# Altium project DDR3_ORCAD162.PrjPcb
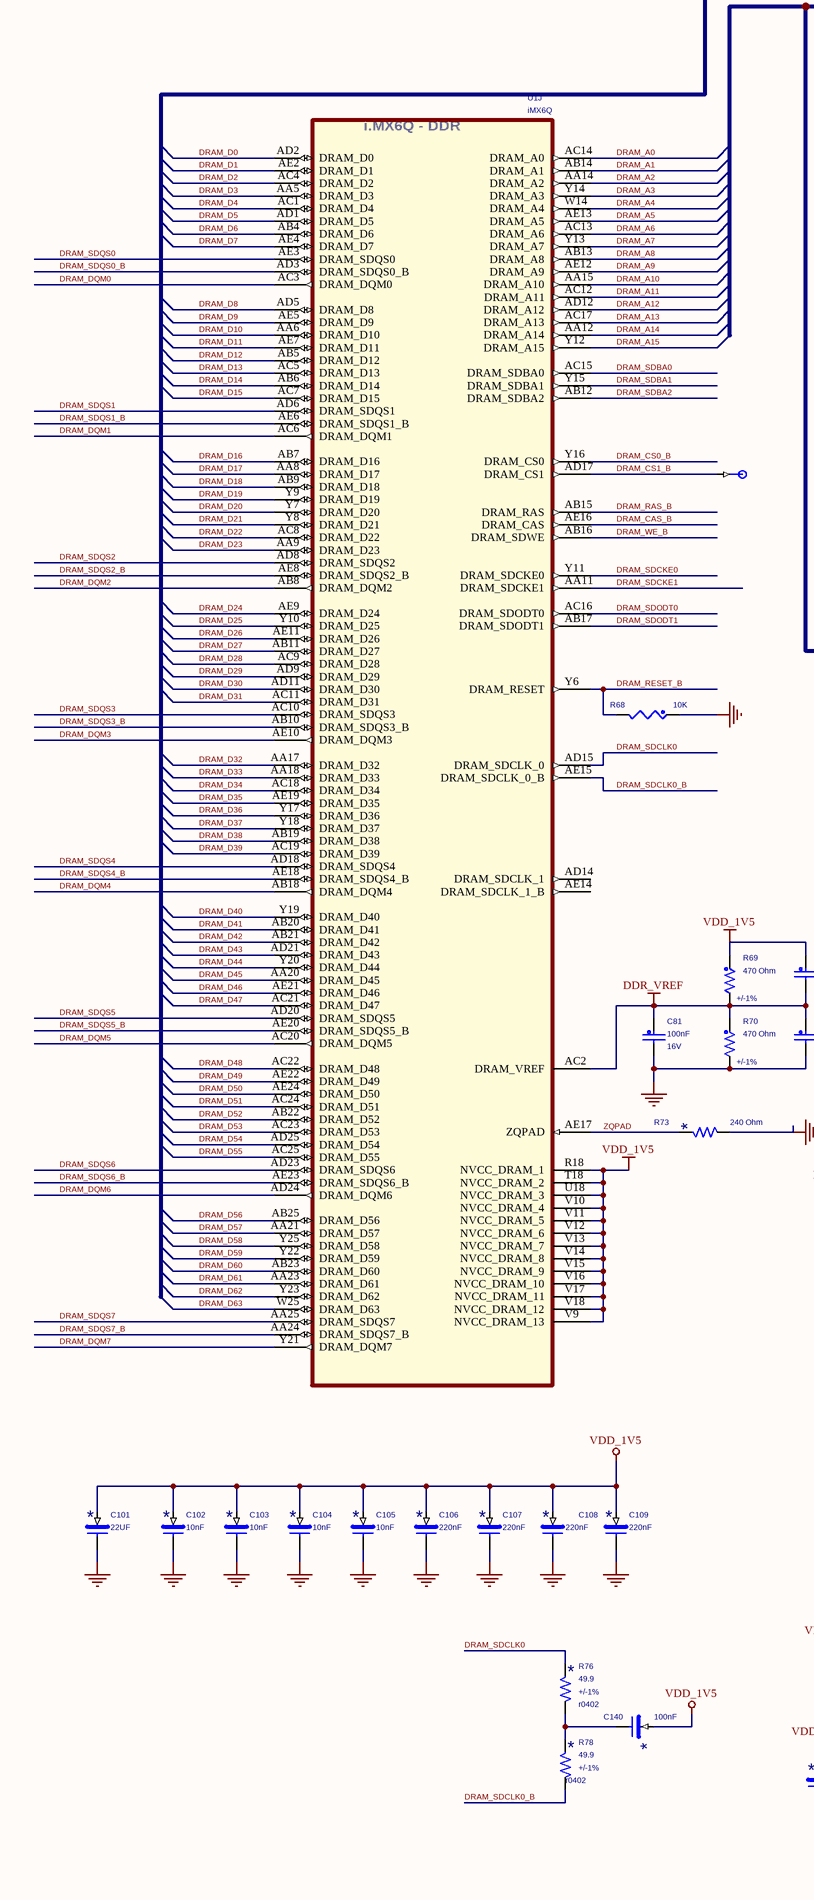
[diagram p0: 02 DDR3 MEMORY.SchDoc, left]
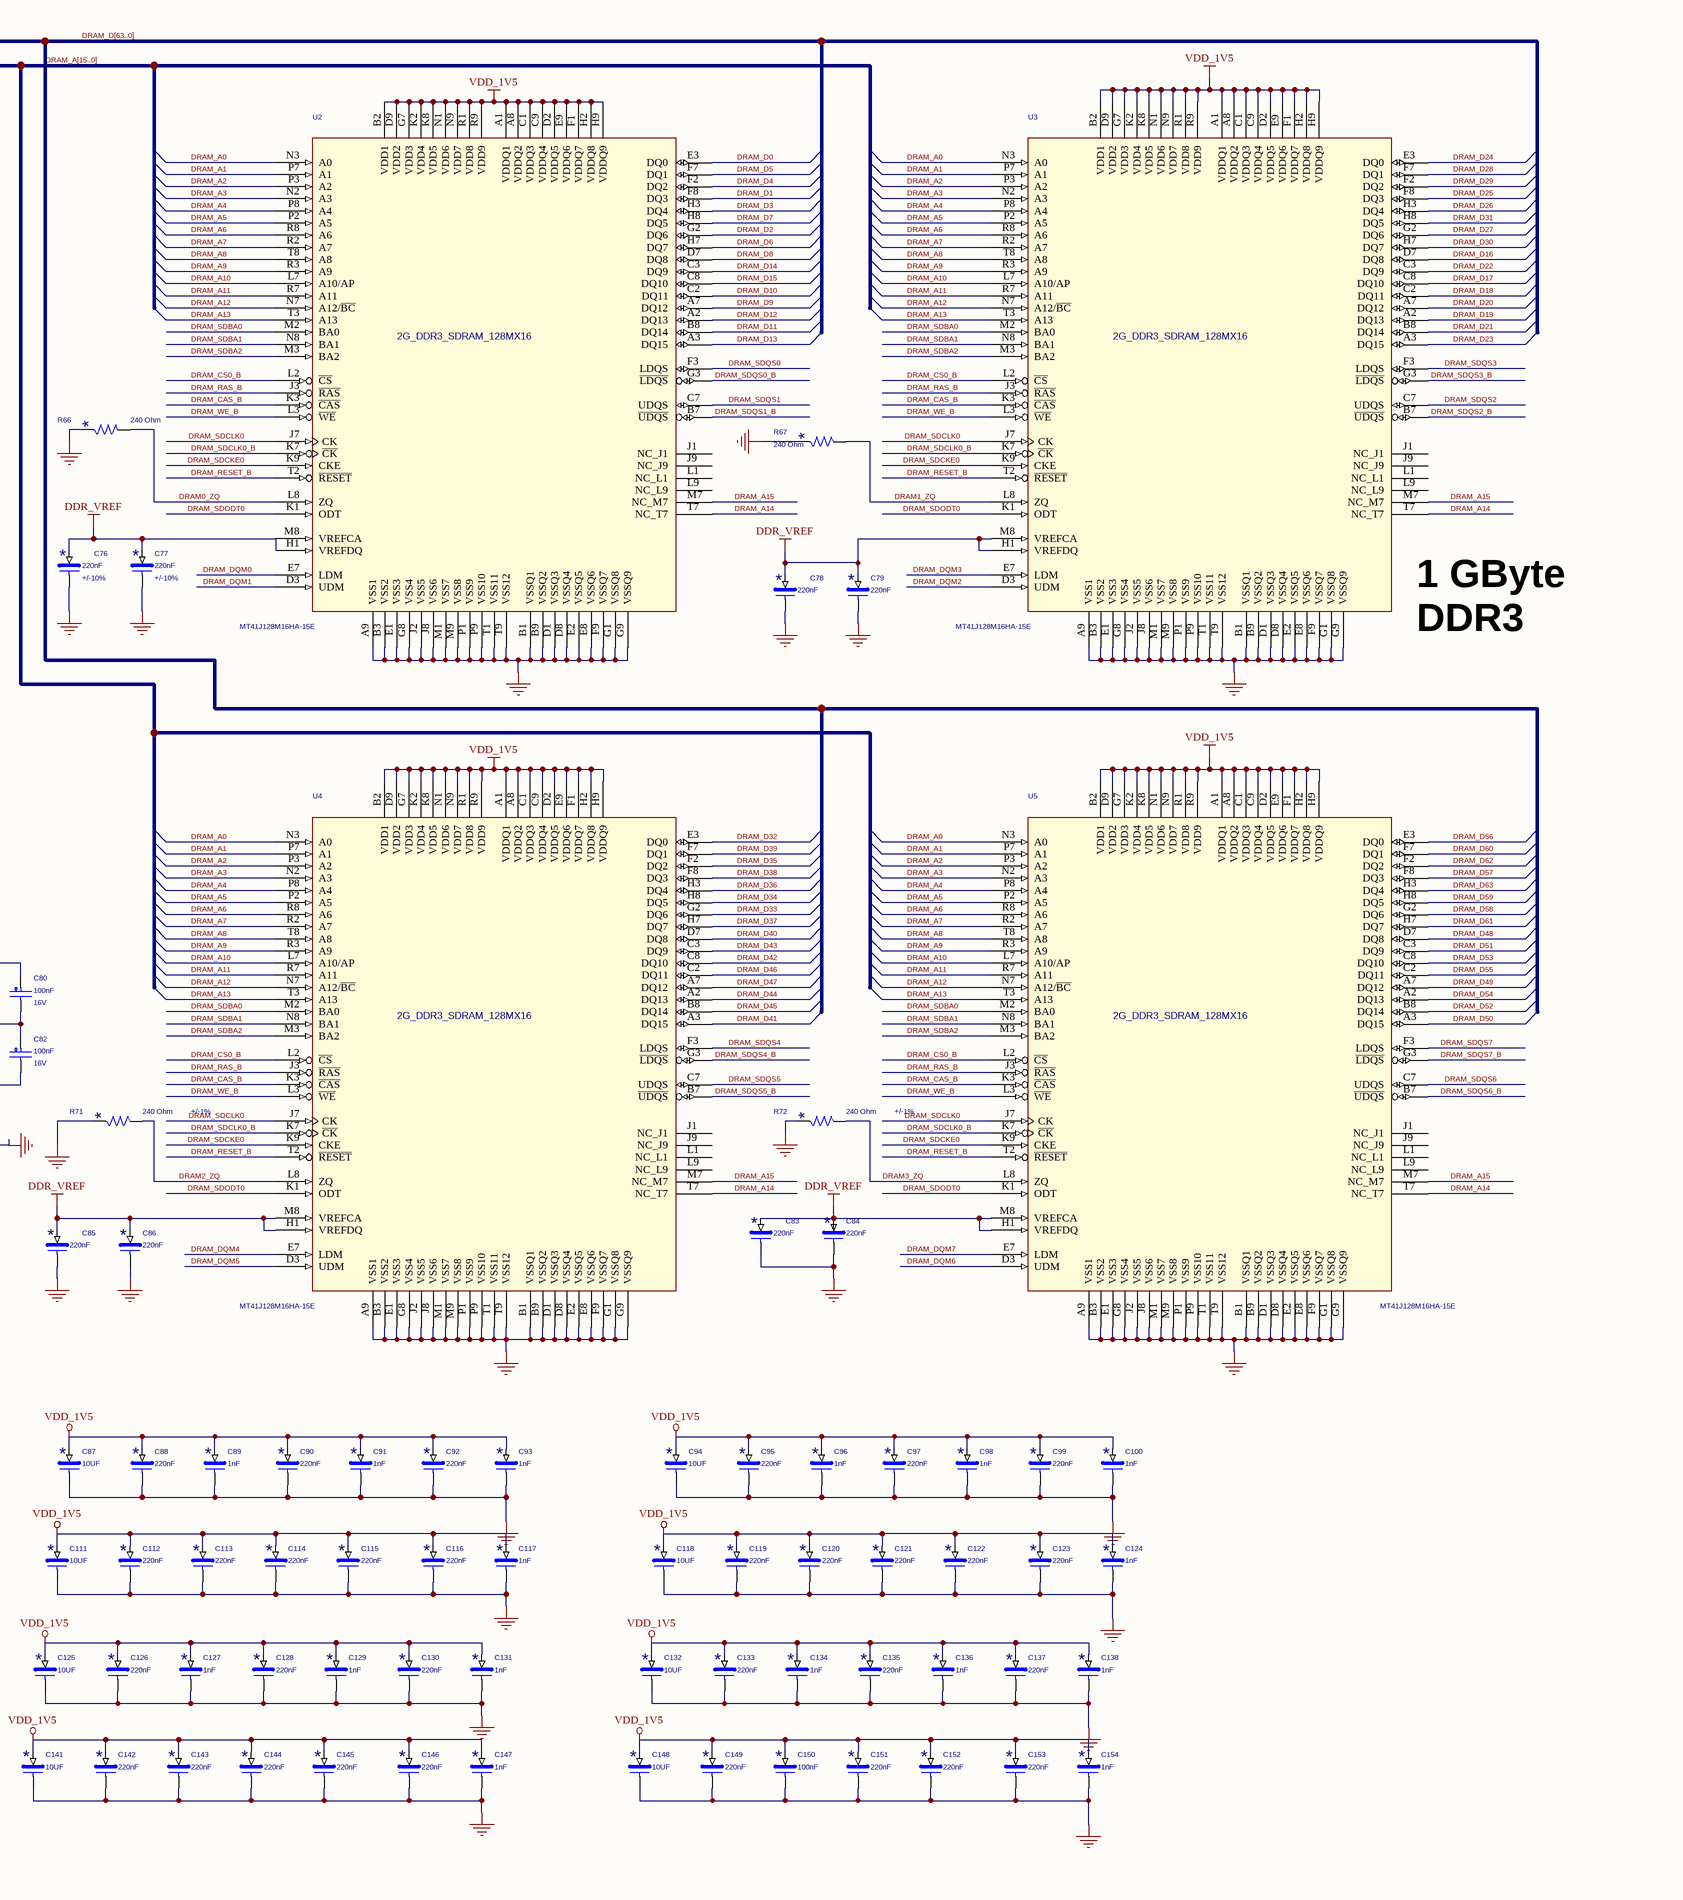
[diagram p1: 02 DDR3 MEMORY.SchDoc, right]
2 sheets, 111 parts. Net scope: global (net labels, ports and power ports of the same name join across sheets).
Sheets:
  02 DDR3 MEMORY.SchDoc
  01 POWER.SchDoc

## Sheet 02 DDR3 MEMORY.SchDoc
size 513 x 386 mm

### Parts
C76  220nF  Tolerance: +/-10%  [C0402]
C77  220nF  Tolerance: +/-10%  [C0402]
C78  220nF  [C0402]
C79  220nF  [C0402]
C80  100nF  WVDC: 16V  [c0402]
C81  100nF  WVDC: 16V  [c0402]
C82  100nF  WVDC: 16V  [c0402]
C83  220nF  [C0402]
C84  220nF  [C0402]
C85  220nF  [C0402]
C86  220nF  [C0402]
C87  10UF  [c0603]
C88  220nF  [C0402]
C89  1nF  [C0402]
C90  220nF  [C0402]
C91  1nF  [C0402]
C92  220nF  [C0402]
C93  1nF  [C0402]
C94  10UF  [c0603]
C95  220nF  [C0402]
C96  1nF  [C0402]
C97  220nF  [C0402]
C98  1nF  [C0402]
C99  220nF  [C0402]
C100  1nF  [C0402]
C101  22UF  [0603_cc]
C102  10nF  [c0402]
C103  10nF  [c0402]
C104  10nF  [c0402]
C105  10nF  [c0402]
C106  220nF  [c0402]
C107  220nF  [c0402]
C108  220nF  [c0402]
C109  220nF  [c0402]
C111  10UF  [c0402]
C112  220nF  [c0402]
C113  220nF  [c0402]
C114  220nF  [c0402]
C115  220nF  [c0402]
C116  220nF  [c0402]
C117  1nF  [c0402]
C118  10UF  [c0603]
C119  220nF  [C0402]
C120  220nF  [C0402]
C121  220nF  [C0402]
C122  220nF  [C0402]
C123  220nF  [C0402]
C124  1nF  [C0402]
C125  10UF  [c0603]
C126  220nF  [C0402]
C127  1nF  [C0402]
C128  220nF  [C0402]
C129  1nF  [C0402]
C130  220nF  [C0402]
C131  1nF  [C0402]
C132  10UF  [c0603]
C133  220nF  [C0402]
C134  1nF  [C0402]
C135  220nF  [C0402]
C136  1nF  [C0402]
C137  220nF  [C0402]
C138  1nF  [C0402]
C140  100nF  [c0402]
C141  10UF  [c0603]
C142  220nF  [C0402]
C143  220nF  [C0402]
C144  220nF  [C0402]
C145  220nF  [C0402]
C146  220nF  [C0402]
C147  1nF  [C0402]
C148  10UF  [c0603]
C149  220nF  [C0402]
C150  100nF  [C0402]
C151  220nF  [C0402]
C152  220nF  [C0402]
C153  220nF  [C0402]
C154  1nF  [C0402]
R66  240 Ohm  [r0402]
R67  240 Ohm  [r0402]
R68  10K  [r0402]
R69  470 Ohm  Tolerance: +/-1%  [r0402]
R70  470 Ohm  Tolerance: +/-1%  [r0402]
R71  240 Ohm  Tolerance: +/-1%  [r0402]
R72  240 Ohm  Tolerance: +/-1%  [r0402]
R73  240 Ohm  [r0402]
R76  49.9  Tolerance: +/-1%  [r0402]
R78  49.9  Tolerance: +/-1%  [r0402]
TP2  TP  [TP]  (value not drawn)
U1  iMX6Q  [skt_bga625_0p8_22x22]  (part J of 12)
U2  MT41J128M16HA-15E  [BGA15X9-96_FS]
U3  MT41J128M16HA-15E  [BGA15X9-96_FS]
U4  MT41J128M16HA-15E  [BGA15X9-96_FS]
U5  MT41J128M16HA-15E  [BGA15X9-96_FS]

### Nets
DDR_VREF: C76.1 C77.1 C78.1 C79.1 C80.2 C81.1 C82.1 C83.1 C84.1 C85.1 C86.1 R69.2 R70.1 U1.AC2(DRAM_VREF) U2.H1(VREFDQ) U2.M8(VREFCA) U3.H1(VREFDQ) U3.M8(VREFCA) U4.H1(VREFDQ) U4.M8(VREFCA) U5.H1(VREFDQ) U5.M8(VREFCA)
GND: C76.2 C77.2 C78.2 C79.2 C81.2 C82.2 C83.2 C84.2 C85.2 C86.2 C87.2 C88.2 C89.2 C90.2 C91.2 C92.2 C93.2 C94.2 C95.2 C96.2 C97.2 C98.2 C99.2 C100.2 C101.2 C102.2 C103.2 C104.2 C105.2 C106.2 C107.2 C108.2 C109.2 C111.2 C112.2 C113.2 C114.2 C115.2 C116.2 C117.2 C118.2 C119.2 C120.2 C121.2 C122.2 C123.2 C124.2 C125.2 C126.2 C127.2 C128.2 C129.2 C130.2 C131.2 C132.2 C133.2 C134.2 C135.2 C136.2 C137.2 C138.2 C141.2 C142.2 C143.2 C144.2 C145.2 C146.2 C147.2 C148.2 C149.2 C150.2 C151.2 C152.2 C153.2 C154.2 R66.1 R67.1 R68.1 R70.2 R71.1 R72.1 R73.2 U2.A9(VSS1) U2.B1(VSSQ1) U2.B3(VSS2) U2.B9(VSSQ2) U2.D1(VSSQ3) U2.D8(VSSQ4) U2.E1(VSS3) U2.E2(VSSQ5) U2.E8(VSSQ6) U2.F9(VSSQ7) U2.G1(VSSQ8) U2.G8(VSS4) U2.G9(VSSQ9) U2.J2(VSS5) U2.J8(VSS6) U2.M1(VSS7) U2.M9(VSS8) U2.P1(VSS9) U2.P9(VSS10) U2.T1(VSS11) U2.T9(VSS12) U3.A9(VSS1) U3.B1(VSSQ1) U3.B3(VSS2) U3.B9(VSSQ2) U3.D1(VSSQ3) U3.D8(VSSQ4) U3.E1(VSS3) U3.E2(VSSQ5) U3.E8(VSSQ6) U3.F9(VSSQ7) U3.G1(VSSQ8) U3.G8(VSS4) U3.G9(VSSQ9) U3.J2(VSS5) U3.J8(VSS6) U3.M1(VSS7) U3.M9(VSS8) U3.P1(VSS9) U3.P9(VSS10) U3.T1(VSS11) U3.T9(VSS12) U4.A9(VSS1) U4.B1(VSSQ1) U4.B3(VSS2) U4.B9(VSSQ2) U4.D1(VSSQ3) U4.D8(VSSQ4) U4.E1(VSS3) U4.E2(VSSQ5) U4.E8(VSSQ6) U4.F9(VSSQ7) U4.G1(VSSQ8) U4.G8(VSS4) U4.G9(VSSQ9) U4.J2(VSS5) U4.J8(VSS6) U4.M1(VSS7) U4.M9(VSS8) U4.P1(VSS9) U4.P9(VSS10) U4.T1(VSS11) U4.T9(VSS12) U5.A9(VSS1) U5.B1(VSSQ1) U5.B3(VSS2) U5.B9(VSSQ2) U5.D1(VSSQ3) U5.D8(VSSQ4) U5.E1(VSS3) U5.E2(VSSQ5) U5.E8(VSSQ6) U5.F9(VSSQ7) U5.G1(VSSQ8) U5.G8(VSS4) U5.G9(VSSQ9) U5.J2(VSS5) U5.J8(VSS6) U5.M1(VSS7) U5.M9(VSS8) U5.P1(VSS9) U5.P9(VSS10) U5.T1(VSS11) U5.T9(VSS12)
VDD_1V5: C80.1 C87.1 C88.1 C89.1 C90.1 C91.1 C92.1 C93.1 C94.1 C95.1 C96.1 C97.1 C98.1 C99.1 C100.1 C101.1 C102.1 C103.1 C104.1 C105.1 C106.1 C107.1 C108.1 C109.1 C111.1 C112.1 C113.1 C114.1 C115.1 C116.1 C117.1 C118.1 C119.1 C120.1 C121.1 C122.1 C123.1 C124.1 C125.1 C126.1 C127.1 C128.1 C129.1 C130.1 C131.1 C132.1 C133.1 C134.1 C135.1 C136.1 C137.1 C138.1 C140.1 C141.1 C142.1 C143.1 C144.1 C145.1 C146.1 C147.1 C148.1 C149.1 C150.1 C151.1 C152.1 C153.1 C154.1 R69.1 U1.R18(NVCC_DRAM_1) U1.T18(NVCC_DRAM_2) U1.U18(NVCC_DRAM_3) U1.V9(NVCC_DRAM_13) U1.V10(NVCC_DRAM_4) U1.V11(NVCC_DRAM_5) U1.V12(NVCC_DRAM_6) U1.V13(NVCC_DRAM_7) U1.V14(NVCC_DRAM_8) U1.V15(NVCC_DRAM_9) U1.V16(NVCC_DRAM_10) U1.V17(NVCC_DRAM_11) U1.V18(NVCC_DRAM_12) U2.A1(VDDQ1) U2.A8(VDDQ2) U2.B2(VDD1) U2.C1(VDDQ3) U2.C9(VDDQ4) U2.D2(VDDQ5) U2.D9(VDD2) U2.E9(VDDQ6) U2.F1(VDDQ7) U2.G7(VDD3) U2.H2(VDDQ8) U2.H9(VDDQ9) U2.K2(VDD4) U2.K8(VDD5) U2.N1(VDD6) U2.N9(VDD7) U2.R1(VDD8) U2.R9(VDD9) U3.A1(VDDQ1) U3.A8(VDDQ2) U3.B2(VDD1) U3.C1(VDDQ3) U3.C9(VDDQ4) U3.D2(VDDQ5) U3.D9(VDD2) U3.E9(VDDQ6) U3.F1(VDDQ7) U3.G7(VDD3) U3.H2(VDDQ8) U3.H9(VDDQ9) U3.K2(VDD4) U3.K8(VDD5) U3.N1(VDD6) U3.N9(VDD7) U3.R1(VDD8) U3.R9(VDD9) U4.A1(VDDQ1) U4.A8(VDDQ2) U4.B2(VDD1) U4.C1(VDDQ3) U4.C9(VDDQ4) U4.D2(VDDQ5) U4.D9(VDD2) U4.E9(VDDQ6) U4.F1(VDDQ7) U4.G7(VDD3) U4.H2(VDDQ8) U4.H9(VDDQ9) U4.K2(VDD4) U4.K8(VDD5) U4.N1(VDD6) U4.N9(VDD7) U4.R1(VDD8) U4.R9(VDD9) U5.A1(VDDQ1) U5.A8(VDDQ2) U5.B2(VDD1) U5.C1(VDDQ3) U5.C9(VDDQ4) U5.D2(VDDQ5) U5.D9(VDD2) U5.E9(VDDQ6) U5.F1(VDDQ7) U5.G7(VDD3) U5.H2(VDDQ8) U5.H9(VDDQ9) U5.K2(VDD4) U5.K8(VDD5) U5.N1(VDD6) U5.N9(VDD7) U5.R1(VDD8) U5.R9(VDD9)
DRAM0_ZQ: R66.2 U2.L8(ZQ)
DRAM1_ZQ: R67.2 U3.L8(ZQ)
DRAM2_ZQ: R71.2 U4.L8(ZQ)
DRAM3_ZQ: R72.2 U5.L8(ZQ)
DRAM_A0: U1.AC14(DRAM_A0) U1.AC22(DRAM_D48) U2.N3(A0) U3.N3(A0) U4.N3(A0) U5.D7(DQ8) U5.N3(A0)  [also labelled DRAM_D48]
DRAM_A1: U1.AB14(DRAM_A1) U1.AE22(DRAM_D49) U2.P7(A1) U3.P7(A1) U4.P7(A1) U5.A7(DQ12) U5.P7(A1)  [also labelled DRAM_D49]
DRAM_A2: U1.AA14(DRAM_A2) U1.AE24(DRAM_D50) U2.P3(A2) U3.P3(A2) U4.P3(A2) U5.A3(DQ15) U5.P3(A2)  [also labelled DRAM_D50]
DRAM_A3: U1.AC24(DRAM_D51) U1.Y14(DRAM_A3) U2.N2(A3) U3.N2(A3) U4.N2(A3) U5.C3(DQ9) U5.N2(A3)  [also labelled DRAM_D51]
DRAM_A4: U1.AB22(DRAM_D52) U1.W14(DRAM_A4) U2.P8(A4) U3.P8(A4) U4.P8(A4) U5.B8(DQ14) U5.P8(A4)  [also labelled DRAM_D52]
DRAM_A5: U1.AC23(DRAM_D53) U1.AE13(DRAM_A5) U2.P2(A5) U3.P2(A5) U4.P2(A5) U5.C8(DQ10) U5.P2(A5)  [also labelled DRAM_D53]
DRAM_A6: U1.AC13(DRAM_A6) U1.AD25(DRAM_D54) U2.R8(A6) U3.R8(A6) U4.R8(A6) U5.A2(DQ13) U5.R8(A6)  [also labelled DRAM_D54]
DRAM_A7: U1.AC25(DRAM_D55) U1.Y13(DRAM_A7) U2.R2(A7) U3.R2(A7) U4.R2(A7) U5.C2(DQ11) U5.R2(A7)  [also labelled DRAM_D55]
DRAM_A8: U1.AB13(DRAM_A8) U1.AB25(DRAM_D56) U2.T8(A8) U3.T8(A8) U4.T8(A8) U5.E3(DQ0) U5.T8(A8)  [also labelled DRAM_D56]
DRAM_A9: U1.AA21(DRAM_D57) U1.AE12(DRAM_A9) U2.R3(A9) U3.R3(A9) U4.R3(A9) U5.F8(DQ3) U5.R3(A9)  [also labelled DRAM_D57]
DRAM_A10: U1.AA15(DRAM_A10) U1.Y25(DRAM_D58) U2.L7(A10/AP) U3.L7(A10/AP) U4.L7(A10/AP) U5.G2(DQ6) U5.L7(A10/AP)  [also labelled DRAM_D58]
DRAM_A11: U1.AC12(DRAM_A11) U1.Y22(DRAM_D59) U2.R7(A11) U3.R7(A11) U4.R7(A11) U5.H8(DQ5) U5.R7(A11)  [also labelled DRAM_D59]
DRAM_A12: U1.AB23(DRAM_D60) U1.AD12(DRAM_A12) U2.N7(A12/~{BC}) U3.N7(A12/~{BC}) U4.N7(A12/~{BC}) U5.F7(DQ1) U5.N7(A12/~{BC})  [also labelled DRAM_D60]
DRAM_A13: U1.AA23(DRAM_D61) U1.AC17(DRAM_A13) U2.T3(A13) U3.T3(A13) U4.T3(A13) U5.H7(DQ7) U5.T3(A13)  [also labelled DRAM_D61]
DRAM_A14: U1.AA12(DRAM_A14) U1.Y23(DRAM_D62) U2.T7(NC_T7) U3.T7(NC_T7) U4.T7(NC_T7) U5.F2(DQ2) U5.T7(NC_T7)  [also labelled DRAM_D62]
DRAM_A15: U1.W25(DRAM_D63) U1.Y12(DRAM_A15) U2.M7(NC_M7) U3.M7(NC_M7) U4.M7(NC_M7) U5.H3(DQ4) U5.M7(NC_M7)  [also labelled DRAM_D63]
DRAM_CAS_B: U1.AE16(DRAM_CAS) U2.K3(~{CAS}) U3.K3(~{CAS}) U4.K3(~{CAS}) U5.K3(~{CAS})
DRAM_CS0_B: U1.Y16(DRAM_CS0) U2.L2(~{CS}) U3.L2(~{CS}) U4.L2(~{CS}) U5.L2(~{CS})
DRAM_CS1_B: TP2.1 U1.AD17(DRAM_CS1)
DRAM_D0: U1.AD2(DRAM_D0) U2.E3(DQ0)
DRAM_D1: U1.AE2(DRAM_D1) U2.F8(DQ3)
DRAM_D2: U1.AC4(DRAM_D2) U2.G2(DQ6)
DRAM_D3: U1.AA5(DRAM_D3) U2.H3(DQ4)
DRAM_D4: U1.AC1(DRAM_D4) U2.F2(DQ2)
DRAM_D5: U1.AD1(DRAM_D5) U2.F7(DQ1)
DRAM_D6: U1.AB4(DRAM_D6) U2.H7(DQ7)
DRAM_D7: U1.AE4(DRAM_D7) U2.H8(DQ5)
DRAM_D8: U1.AD5(DRAM_D8) U2.D7(DQ8)
DRAM_D9: U1.AE5(DRAM_D9) U2.A7(DQ12)
DRAM_D10: U1.AA6(DRAM_D10) U2.C2(DQ11)
DRAM_D11: U1.AE7(DRAM_D11) U2.B8(DQ14)
DRAM_D12: U1.AB5(DRAM_D12) U2.A2(DQ13)
DRAM_D13: U1.AC5(DRAM_D13) U2.A3(DQ15)
DRAM_D14: U1.AB6(DRAM_D14) U2.C3(DQ9)
DRAM_D15: U1.AC7(DRAM_D15) U2.C8(DQ10)
DRAM_D16: U1.AB7(DRAM_D16) U3.D7(DQ8)
DRAM_D17: U1.AA8(DRAM_D17) U3.C8(DQ10)
DRAM_D18: U1.AB9(DRAM_D18) U3.C2(DQ11)
DRAM_D19: U1.Y9(DRAM_D19) U3.A2(DQ13)
DRAM_D20: U1.Y7(DRAM_D20) U3.A7(DQ12)
DRAM_D21: U1.Y8(DRAM_D21) U3.B8(DQ14)
DRAM_D22: U1.AC8(DRAM_D22) U3.C3(DQ9)
DRAM_D23: U1.AA9(DRAM_D23) U3.A3(DQ15)
DRAM_D24: U1.AE9(DRAM_D24) U3.E3(DQ0)
DRAM_D25: U1.Y10(DRAM_D25) U3.F8(DQ3)
DRAM_D26: U1.AE11(DRAM_D26) U3.H3(DQ4)
DRAM_D27: U1.AB11(DRAM_D27) U3.G2(DQ6)
DRAM_D28: U1.AC9(DRAM_D28) U3.F7(DQ1)
DRAM_D29: U1.AD9(DRAM_D29) U3.F2(DQ2)
DRAM_D30: U1.AD11(DRAM_D30) U3.H7(DQ7)
DRAM_D31: U1.AC11(DRAM_D31) U3.H8(DQ5)
DRAM_D32: U1.AA17(DRAM_D32) U4.E3(DQ0)
DRAM_D33: U1.AA18(DRAM_D33) U4.G2(DQ6)
DRAM_D34: U1.AC18(DRAM_D34) U4.H8(DQ5)
DRAM_D35: U1.AE19(DRAM_D35) U4.F2(DQ2)
DRAM_D36: U1.Y17(DRAM_D36) U4.H3(DQ4)
DRAM_D37: U1.Y18(DRAM_D37) U4.H7(DQ7)
DRAM_D38: U1.AB19(DRAM_D38) U4.F8(DQ3)
DRAM_D39: U1.AC19(DRAM_D39) U4.F7(DQ1)
DRAM_D40: U1.Y19(DRAM_D40) U4.D7(DQ8)
DRAM_D41: U1.AB20(DRAM_D41) U4.A3(DQ15)
DRAM_D42: U1.AB21(DRAM_D42) U4.C8(DQ10)
DRAM_D43: U1.AD21(DRAM_D43) U4.C3(DQ9)
DRAM_D44: U1.Y20(DRAM_D44) U4.A2(DQ13)
DRAM_D45: U1.AA20(DRAM_D45) U4.B8(DQ14)
DRAM_D46: U1.AE21(DRAM_D46) U4.C2(DQ11)
DRAM_D47: U1.AC21(DRAM_D47) U4.A7(DQ12)
DRAM_DQM0: U1.AC3(DRAM_DQM0) U2.E7(LDM)
DRAM_DQM1: U1.AC6(DRAM_DQM1) U2.D3(UDM)
DRAM_DQM2: U1.AB8(DRAM_DQM2) U3.D3(UDM)
DRAM_DQM3: U1.AE10(DRAM_DQM3) U3.E7(LDM)
DRAM_DQM4: U1.AB18(DRAM_DQM4) U4.E7(LDM)
DRAM_DQM5: U1.AC20(DRAM_DQM5) U4.D3(UDM)
DRAM_DQM6: U1.AD24(DRAM_DQM6) U5.D3(UDM)
DRAM_DQM7: U1.Y21(DRAM_DQM7) U5.E7(LDM)
DRAM_RAS_B: U1.AB15(DRAM_RAS) U2.J3(~{RAS}) U3.J3(~{RAS}) U4.J3(~{RAS}) U5.J3(~{RAS})
DRAM_RESET_B: R68.2 U1.Y6(DRAM_RESET) U2.T2(~{RESET}) U3.T2(~{RESET}) U4.T2(~{RESET}) U5.T2(~{RESET})
DRAM_SDBA0: U1.AC15(DRAM_SDBA0) U2.M2(BA0) U3.M2(BA0) U4.M2(BA0) U5.M2(BA0)
DRAM_SDBA1: U1.Y15(DRAM_SDBA1) U2.N8(BA1) U3.N8(BA1) U4.N8(BA1) U5.N8(BA1)
DRAM_SDBA2: U1.AB12(DRAM_SDBA2) U2.M3(BA2) U3.M3(BA2) U4.M3(BA2) U5.M3(BA2)
DRAM_SDCKE0: U1.Y11(DRAM_SDCKE0) U2.K9(CKE) U3.K9(CKE) U4.K9(CKE) U5.K9(CKE)
DRAM_SDCKE1: U1.AA11(DRAM_SDCKE1)
DRAM_SDCLK0: R76.1 U1.AD15(DRAM_SDCLK_0) U2.J7(CK) U3.J7(CK) U4.J7(CK) U5.J7(CK)
DRAM_SDCLK0_B: R78.2 U1.AE15(DRAM_SDCLK_0_B) U2.K7(~{CK}) U3.K7(~{CK}) U4.K7(~{CK}) U5.K7(~{CK})
DRAM_SDODT0: U1.AC16(DRAM_SDODT0) U2.K1(ODT) U3.K1(ODT) U4.K1(ODT) U5.K1(ODT)
DRAM_SDODT1: U1.AB17(DRAM_SDODT1)
DRAM_SDQS0: U1.AE3(DRAM_SDQS0) U2.F3(LDQS)
DRAM_SDQS0_B: U1.AD3(DRAM_SDQS0_B) U2.G3(~{LDQS})
DRAM_SDQS1: U1.AD6(DRAM_SDQS1) U2.C7(UDQS)
DRAM_SDQS1_B: U1.AE6(DRAM_SDQS1_B) U2.B7(~{UDQS})
DRAM_SDQS2: U1.AD8(DRAM_SDQS2) U3.C7(UDQS)
DRAM_SDQS2_B: U1.AE8(DRAM_SDQS2_B) U3.B7(~{UDQS})
DRAM_SDQS3: U1.AC10(DRAM_SDQS3) U3.F3(LDQS)
DRAM_SDQS3_B: U1.AB10(DRAM_SDQS3_B) U3.G3(~{LDQS})
DRAM_SDQS4: U1.AD18(DRAM_SDQS4) U4.F3(LDQS)
DRAM_SDQS4_B: U1.AE18(DRAM_SDQS4_B) U4.G3(~{LDQS})
DRAM_SDQS5: U1.AD20(DRAM_SDQS5) U4.C7(UDQS)
DRAM_SDQS5_B: U1.AE20(DRAM_SDQS5_B) U4.B7(~{UDQS})
DRAM_SDQS6: U1.AD23(DRAM_SDQS6) U5.C7(UDQS)
DRAM_SDQS6_B: U1.AE23(DRAM_SDQS6_B) U5.B7(~{UDQS})
DRAM_SDQS7: U1.AA25(DRAM_SDQS7) U5.F3(LDQS)
DRAM_SDQS7_B: U1.AA24(DRAM_SDQS7_B) U5.G3(~{LDQS})
DRAM_WE_B: U1.AB16(DRAM_SDWE) U2.L3(~{WE}) U3.L3(~{WE}) U4.L3(~{WE}) U5.L3(~{WE})
ZQPAD: R73.1 U1.AE17(ZQPAD)
NetC140_2: C140.2 R76.2 R78.1

Not connected (* = marked no-connect by the designer): U1 AD14(DRAM_SDCLK_1) AE14(DRAM_SDCLK_1_B); U2 J1(NC_J1) J9(NC_J9) L1(NC_L1) L9(NC_L9); U3 J1(NC_J1) J9(NC_J9) L1(NC_L1) L9(NC_L9); U4 J1(NC_J1) J9(NC_J9) L1(NC_L1) L9(NC_L9); U5 J1(NC_J1) J9(NC_J9) L1(NC_L1) L9(NC_L9)

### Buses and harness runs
bus DRAM_A[15..0] = DRAM_D[63..0]

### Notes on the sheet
- (near U3) 1 GByte
  DDR3

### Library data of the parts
C76 = CAP: CAP,220nF,+/-20%,X5R,6.3V,G,SMD0201; Foxconn Part Number: 620115S00-015-G; Part Number: 62010KD00-011-G; Mfg Part Number: GRM033R60J224ME15D; VPN: 620115S00-VPN-G; PBDE: 1000; CD: 100; Green State: C5; KEYID: 20070321-51853; HHPN: STDPN; ONLY_DATASHEETNAME: YAGEO_CC0603KRX7R7BB224_DS.pdf; Remark: Reserved; Relex Subcategory: 3; Relex Category: 4; Approval Status: A; Mfg: MURATA
C77 = CAP: CAP,220nF,+/-20%,X5R,6.3V,G,SMD0201; Mfg Part Number: GRM033R60J224ME15D; Part Number: 62010KD00-011-G; Foxconn Part Number: 620115S00-015-G; Mfg: MURATA; Sub System: Reserved; Approval Status: A; Relex Category: 4; Relex Subcategory: 3; ONLY_DATASHEETNAME: YAGEO_CC0603KRX7R7BB224_DS.pdf; HHPN: STDPN; KEYID: 20070321-51853; Green State: C5; PB: 1000; CD: 100; VPN: 620115S00-VPN-G
C78 C83 C85 C108 C109 = CAP: CAP,220nF,+/-20%,X5R,6.3V,G,SMD0201; Foxconn Part Number: 620115S00-015-G; Part Number: 62010KD00-011-G; Mfg Part Number: GRM033R60J224ME15D; Tolerance: +/-10%; VPN: 620115S00-VPN-G; PBDE: 1000; CD: 100; Green State: C5; KEYID: 20070321-51853; HHPN: STDPN; ONLY_DATASHEETNAME: YAGEO_CC0603KRX7R7BB224_DS.pdf; Remark: Reserved; Relex Subcategory: 3; Relex Category: 4; Approval Status: A; Mfg: MURATA
C79 C84 C86 C107 = CAP: CAP,220nF,+/-20%,X5R,6.3V,G,SMD0201; Mfg Part Number: GRM033R60J224ME15D; Part Number: 62010KD00-011-G; Foxconn Part Number: 620115S00-015-G; Tolerance: +/-10%; Mfg: MURATA; Sub System: Reserved; Approval Status: A; Relex Category: 4; Relex Subcategory: 3; ONLY_DATASHEETNAME: YAGEO_CC0603KRX7R7BB224_DS.pdf; HHPN: STDPN; KEYID: 20070321-51853; Green State: C5; PB: 1000; CD: 100; VPN: 620115S00-VPN-G
C80 C82 = CAP_NP: CAP CER 0.1UF 16V 10% X7R 0402; CLASS: DISCRETE; SIGNAL_MODEL: DEFAULT_CAPACITOR_100000pF_2_1; PRIORITY_PN: 021-00274; FPLIST: CC0402_25,CC0402_HD,0402_CC; CAD_APPROVED: Yes; MFG_PN01: C0402C104K4RAC; MFG_NAME01: KEMET; AGILE_PN: 150-75182
C81 = CAP_NP: CAP CER 0.1UF 16V 10% X7R 0402; CLASS: DISCRETE; AGILE_PN: 150-75182; MFG_NAME01: KEMET; MFG_PN01: C0402C104K4RAC; CAD_APPROVED: Yes; FPLIST: CC0402_25,CC0402_HD,0402_CC; PRIORITY_PN: 021-00274; SIGNAL_MODEL: DEFAULT_CAPACITOR_100000pF_2_1
C87 C94 C111 C125 C132 = CC0603MRX5R5BB106: CAP,10uF,+/-20%,X5R,10V,G,SMD0603; Foxconn Part Number: 620112400-023-G; Part Number: 62010L000-011-G; Mfg Part Number: LMK107BJ106MALTD; Tolerance: 6.3V,X5R,+/-20%; VPN: 620112400-VPN-G; HHPN: STDPN; ONLY_DATASHEETNAME: YAGEO_CC0603MRX5R5BB106_DS.pdf; Remark: Reserved; Relex Subcategory: 3; Relex Category: 4; Approval Status: E; CCL: for MID; Mfg: TAIYO
C88 C92 C95 C99 C112 C116 C122 C126 C130 C133 C137 C140 C145 C152 = CAP: CAP,100nF,+/-10%,X5R,10V,G,SMD0201; Mfg Part Number: CC0201KRX5R6BB104; Part Number: 62-01030380-00-011; Foxconn Part Number: 620112U00-011-G; Tolerance: 16V, X7R, +/-10%; Mfg: YAGEO; Sub System: Reserved; Approval Status: A; Relex Category: 4; Relex Subcategory: 3; ONLY_DATASHEETNAME: MLCC.pdf; HHPN: 62-01030380-00-011-G; KEYID: 1667; Green State: C5; PB: 1000; CD: 100; VPN: 620112U00-VPN-G
C89 C96 C127 C134 = CAP: CAP,1nF,+/-10%,X7R,25V,G,SMD0402; Mfg Part Number: CC0201KRX7R8BB102; Part Number: 62-01030114-00-011; Foxconn Part Number: 62010LF00-011-G; Tolerance: 50V, X7R, +/-10%; Mfg: YAGEO; Sub System: Reserved; Approval Status: A; Relex Category: 4; Relex Subcategory: 3; ONLY_DATASHEETNAME: MLCC.pdf; HHPN: 62-01030114-00-011-G; KEYID: 1705; Green State: C5; PB: 1000; CD: 100; VPN: 62010LF00-VPN-G
C90 C97 C128 C135 = CAP: CAP,100nF,+/-10%,X5R,10V,G,SMD0201; Mfg Part Number: CC0201KRX5R6BB104; Part Number: 62-01030380-00-011; Foxconn Part Number: 620112U00-011-G; Tolerance: 16V, X7R, +/-10%; Mfg: YAGEO; Sub System: Rserved; Approval Status: A; Relex Category: 4; Relex Subcategory: 3; Remark: Dummy; ONLY_DATASHEETNAME: MLCC.pdf; HHPN: 62-01030380-00-011-G; KEYID: 1667; Green State: C5; PB: 1000; CD: 100; VPN: 620112U00-VPN-G
C91 C98 C129 C136 = CAP: CAP,1nF,+/-10%,X7R,25V,G,SMD0201; Foxconn Part Number: 62010LF00-011-G; Part Number: 62-01030114-00-011; Mfg Part Number: CC0201KRX7R8BB102; Tolerance: 50V, X7R, +/-10%; Item Status: A; VPN: 62010LF00-VPN-G; PBDE: 1000; CD: 100; Green State: C5; KEYID: 1705; HHPN: 62-01030114-00-011-G; ONLY_DATASHEETNAME: MLCC.pdf; Remark: Reserved; Relex Subcategory: 3; Relex Category: 4; Sub System: Rserved; Mfg: YAGEO
C93 C100 C117 C131 C138 = CAP: CAP,1nF,+/-10%,X7R,25V,G,SMD0201; Foxconn Part Number: 62010LF00-011-G; Part Number: 62-01030114-00-011; Mfg Part Number: CC0201KRX7R8BB102; Tolerance: 50V, X7R, +/-10%; VPN: 62010LF00-VPN-G; PBDE: 1000; CD: 100; Green State: C5; KEYID: 1705; HHPN: 62-01030114-00-011-G; ONLY_DATASHEETNAME: MLCC.pdf; Remark: Reserved; Relex Subcategory: 3; Relex Category: 4; Approval Status: A; Mfg: YAGEO
C101 = CAP: CAP CER 22UF 4V 20% X5R 0603; Foxconn Part Number: 620108H00-015-G; Part Number: 62-01020059-00-015; Mfg Part Number: GRM21BR60J226M; Tolerance: 6.3V,X5R,+/-20%; Item Status: A; VPN: 620108H00-VPN-G; PBDE: 5; Green State: C5; KEYID: 20050824-04221; HHPN: 62-01020059-00-015-G; PCB_FOOTPRINT_BEFORE: c0805h14; ONLY_DATASHEETNAME: MURATA_GRM21BR60J226ME39L_DS.pdf; Remark: Reserved; Relex Subcategory: 1; Relex Category: 4; Mfg: MURATA
C102-C104 = GRM155R71H103K: CAP,10nF,+/-10%,X7R,10V,G,SMD0201; Mfg Part Number: CC0201KRX7R6BB103; Part Number: 62010QB00-015-G; Foxconn Part Number: 62010LA00-011-G; Mfg: YAGEO; Sub System: Reserved; Approval Status: E; Relex Category: 4; Relex Subcategory: 2; ONLY_DATASHEETNAME: MURATA_GRM155R71H103K_DS.pdf; HHPN: STDPN; KEYID: 20071225-23718; VPN: 62010LA00-VPN-G
C105 = GRM155R71H103K: CAP,10nF,+/-10%,X7R,10V,G,SMD0201; Mfg Part Number: CC0201KRX7R6BB103; Part Number: 62010QB00-015-G; Mfg: YAGEO; Sub System: Reserved; Approval Status: E; Relex Category: 4; Relex Subcategory: 2; ONLY_DATASHEETNAME: MURATA_GRM155R71H103K_DS.pdf; HHPN: STDPN
C106 = CAP: CAP,220nF,+/-20%,X5R,6.3V,G,SMD0201; Foxconn Part Number: 620115S00-015-G; Part Number: 62010KD00-011-G; Mfg Part Number: GRM033R60J224ME15D; Tolerance: +/-10%; VPN: 620115S00-VPN-G; PBDE: 1000; CD: 100; Green State: C5; KEYID: 20070321-51853; HHPN: STDPN; ONLY_DATASHEETNAME: YAGEO_CC0603KRX7R7BB224_DS.pdf; Relex Subcategory: 3; Relex Category: 4; Approval Status: A; Sub System: Reserved; Mfg: MURATA
C113 C121 C144 C150 C151 = CAP: CAP,100nF,+/-10%,X5R,10V,G,SMD0201; Mfg Part Number: CC0201KRX5R6BB104; Part Number: 62-01030380-00-011; Foxconn Part Number: 620112U00-011-G; Tolerance: 16V, X7R, +/-10%; Mfg: YAGEO; Sub System: Rserved; Approval Status: A; Relex Category: 4; Relex Subcategory: 3; Remark: Reserved; ONLY_DATASHEETNAME: MLCC.pdf; HHPN: 62-01030380-00-011-G; KEYID: 1667; Green State: C5; PB: 1000; CD: 100; VPN: 620112U00-VPN-G
C114 C120 C143 = CAP: CAP,100nF,+/-10%,X5R,10V,G,SMD0201; Foxconn Part Number: 620112U00-011-G; Part Number: 62-01030380-00-011; Mfg Part Number: CC0201KRX5R6BB104; Tolerance: 16V, X7R, +/-10%; VPN: 620112U00-VPN-G; PBDE: 1000; CD: 100; Green State: C5; KEYID: 1667; HHPN: 62-01030380-00-011-G; ONLY_DATASHEETNAME: MLCC.pdf; Remark: Reserved; Relex Subcategory: 3; Relex Category: 4; Approval Status: A; Sub System: Rserved; Mfg: YAGEO
C115 C119 C123 C142 C146 C149 C153 = CAP: CAP,100nF,+/-10%,X5R,10V,G,SMD0201; Foxconn Part Number: 620112U00-011-G; Part Number: 62-01030380-00-011; Mfg Part Number: CC0201KRX5R6BB104; Tolerance: 16V, X7R, +/-10%; VPN: 620112U00-VPN-G; PBDE: 1000; CD: 100; Green State: C5; KEYID: 1667; HHPN: 62-01030380-00-011-G; ONLY_DATASHEETNAME: MLCC.pdf; Remark: Reserved; Relex Subcategory: 3; Relex Category: 4; Approval Status: A; Mfg: YAGEO
C118 C141 C148 = CC0603MRX5R5BB106: CAP,10uF,+/-20%,X5R,10V,G,SMD0603; Mfg Part Number: LMK107BJ106MALTD; Part Number: 62010L000-011-G; Foxconn Part Number: 620112400-023-G; Tolerance: 6.3V,X5R,+/-20%; Item Status: E; Mfg: TAIYO; CCL: for MID; Sub System: Reserved; Relex Category: 4; Relex Subcategory: 3; ONLY_DATASHEETNAME: YAGEO_CC0603MRX5R5BB106_DS.pdf; HHPN: STDPN; VPN: 620112400-VPN-G
C124 C147 C154 = CAP: CAP,1nF,+/-10%,X7R,25V,G,SMD0201; Mfg Part Number: CC0201KRX7R8BB102; Part Number: 62-01030114-00-011; Foxconn Part Number: 62010LF00-011-G; Tolerance: 50V, X7R, +/-10%; Mfg: YAGEO; Sub System: Reserved; Approval Status: A; Relex Category: 4; Relex Subcategory: 3; ONLY_DATASHEETNAME: MLCC.pdf; HHPN: 62-01030114-00-011-G; KEYID: 1705; Green State: C5; PB: 1000; CD: 100; VPN: 62010LF00-VPN-G
R66 R67 R73 = RC0402FR-07240RL: RES,240 Ohm,+/-1%,1/20W,G,SMD0201; Foxconn Part Number: 610135N00-011-G; Part Number: 61011T800-011-G; Mfg Part Number: RC0201FR-07240RL; VPN: 610135N00-VPN-G; PBDE: 5; CR6: 2; PB: 230316.6; Green State: C2; KEYID: 20071222-91056; HHPN: STDPN; ONLY_DATASHEETNAME: YAGEO_RC0402FR-07240RL_DS.pdf; Remark: Reserved; Relex Subcategory: 1; Relex Category: 3; Approval Status: E; Mfg: YAGEO
R68 = RES: RES MF 10.0K 1/16W 1% 0402; CLASS: DISCRETE; AGILE_PN: 470-75416; MFG_NAME01: VISHAY INTERTECHNOLOGY; MFG_PN01: CRCW040210K0FKED; CAD_APPROVED: Yes; FPLIST: RC0402,rc0402_frs; PRIORITY_PN: 006-00552; ROOM: KEYPAD; SIGNAL_MODEL: DEFAULT_RESISTOR_10000OHM_2_1
R69 R70 = RC0603FR-07470RL: RES,470 Ohm,+/-1%,1/20W,G,SMD0201; Foxconn Part Number: 61012RN00-011-G; Part Number: 61-01000377-01-011; Mfg Part Number: RC0201FR-07470RL; VPN: 61012RN00-VPN-G; PBDE: 1000; CD: 100; PB: 230317; Green State: C5; KEYID: 20060509-81844; HHPN: 61-01000377-01-011-G; PCB_FOOTPRINT_BEFORE: r0603h6; ONLY_DATASHEETNAME: YAGEO_RC0603FR_07470RL_DS.pdf; Remark: Reserved; Relex Subcategory: 2; Relex Category: 3; Approval Status: E; CCL: LF; Mfg: YAGEO
R71 R72 = RC0402FR-07240RL: RES,240 Ohm,+/-1%,1/20W,G,SMD0201; Mfg Part Number: RC0201FR-07240RL; Part Number: 61011T800-011-G; Foxconn Part Number: 610135N00-011-G; Mfg: YAGEO; Sub System: Reserved; Approval Status: E; Relex Category: 3; Relex Subcategory: 1; ONLY_DATASHEETNAME: YAGEO_RC0402FR-07240RL_DS.pdf; HHPN: STDPN; KEYID: 20071222-91056; Green State: C2; PB: 230316.6; CD: 2; PBB: 5; VPN: 610135N00-VPN-G
R76 R78 = RC0402FR-0749R9L: RES,49.9Ohm,+/-1%,1/20W,G,SMD0201; Foxconn Part Number: 61011EM00-011-G; Part Number: 61-01000833-02-011; Mfg Part Number: RC0201FR-0749R9L; VPN: 61011EM00-VPN-G; PBDE: 1000; CD: 100; Green State: C5; KEYID: 4987; HHPN: 61-01000833-02-011-G; ONLY_DATASHEETNAME: YAGEO-RC0402FR-0749R9L-DS.pdf; Remark: Reserved; Relex Subcategory: 2; Relex Category: 3; Approval Status: E; CCL: LF; Mfg: YAGEO
TP2 = TP_0: TEST POINT; Critical_Part: No; Part Number: Waiting Foxconn Part Number; Vendor: Waiting; QVL_Approve: None; Remark: Dummy
U1 = PCIMX6Q6VV1A_0: IC MCU MX6QUAD ARM CORTEX-A9 FCLBGA624; CAD_APPROVED: Yes; MFG_PN01: PCIMX6Q0AVT01A; MFG_NAME01: FREESCALE SEMICONDUCTOR; AGILE_PN: 344-01218
U2-U4 = 2G_DDR3_SDRAM_128MX16_96P: IC MEM DDR3 SDRAM 2Gb 128MX16 1.5V FBGA96; AGILE_PN: 334-77333; MFG_NAME01: MICRON; MFG_PN01: MT41J128M16HA-15E:D; CAD_APPROVED: Yes
U5 = 2G_DDR3_SDRAM_128MX16_96P: IC MEM DDR3 SDRAM 2Gb 128MX16 1.5V FBGA96; CAD_APPROVED: Yes; MFG_PN01: MT41J128M16HA-15E:D; MFG_NAME01: MICRON; AGILE_PN: 334-77333

## Sheet 01 POWER.SchDoc
size 513 x 386 mm
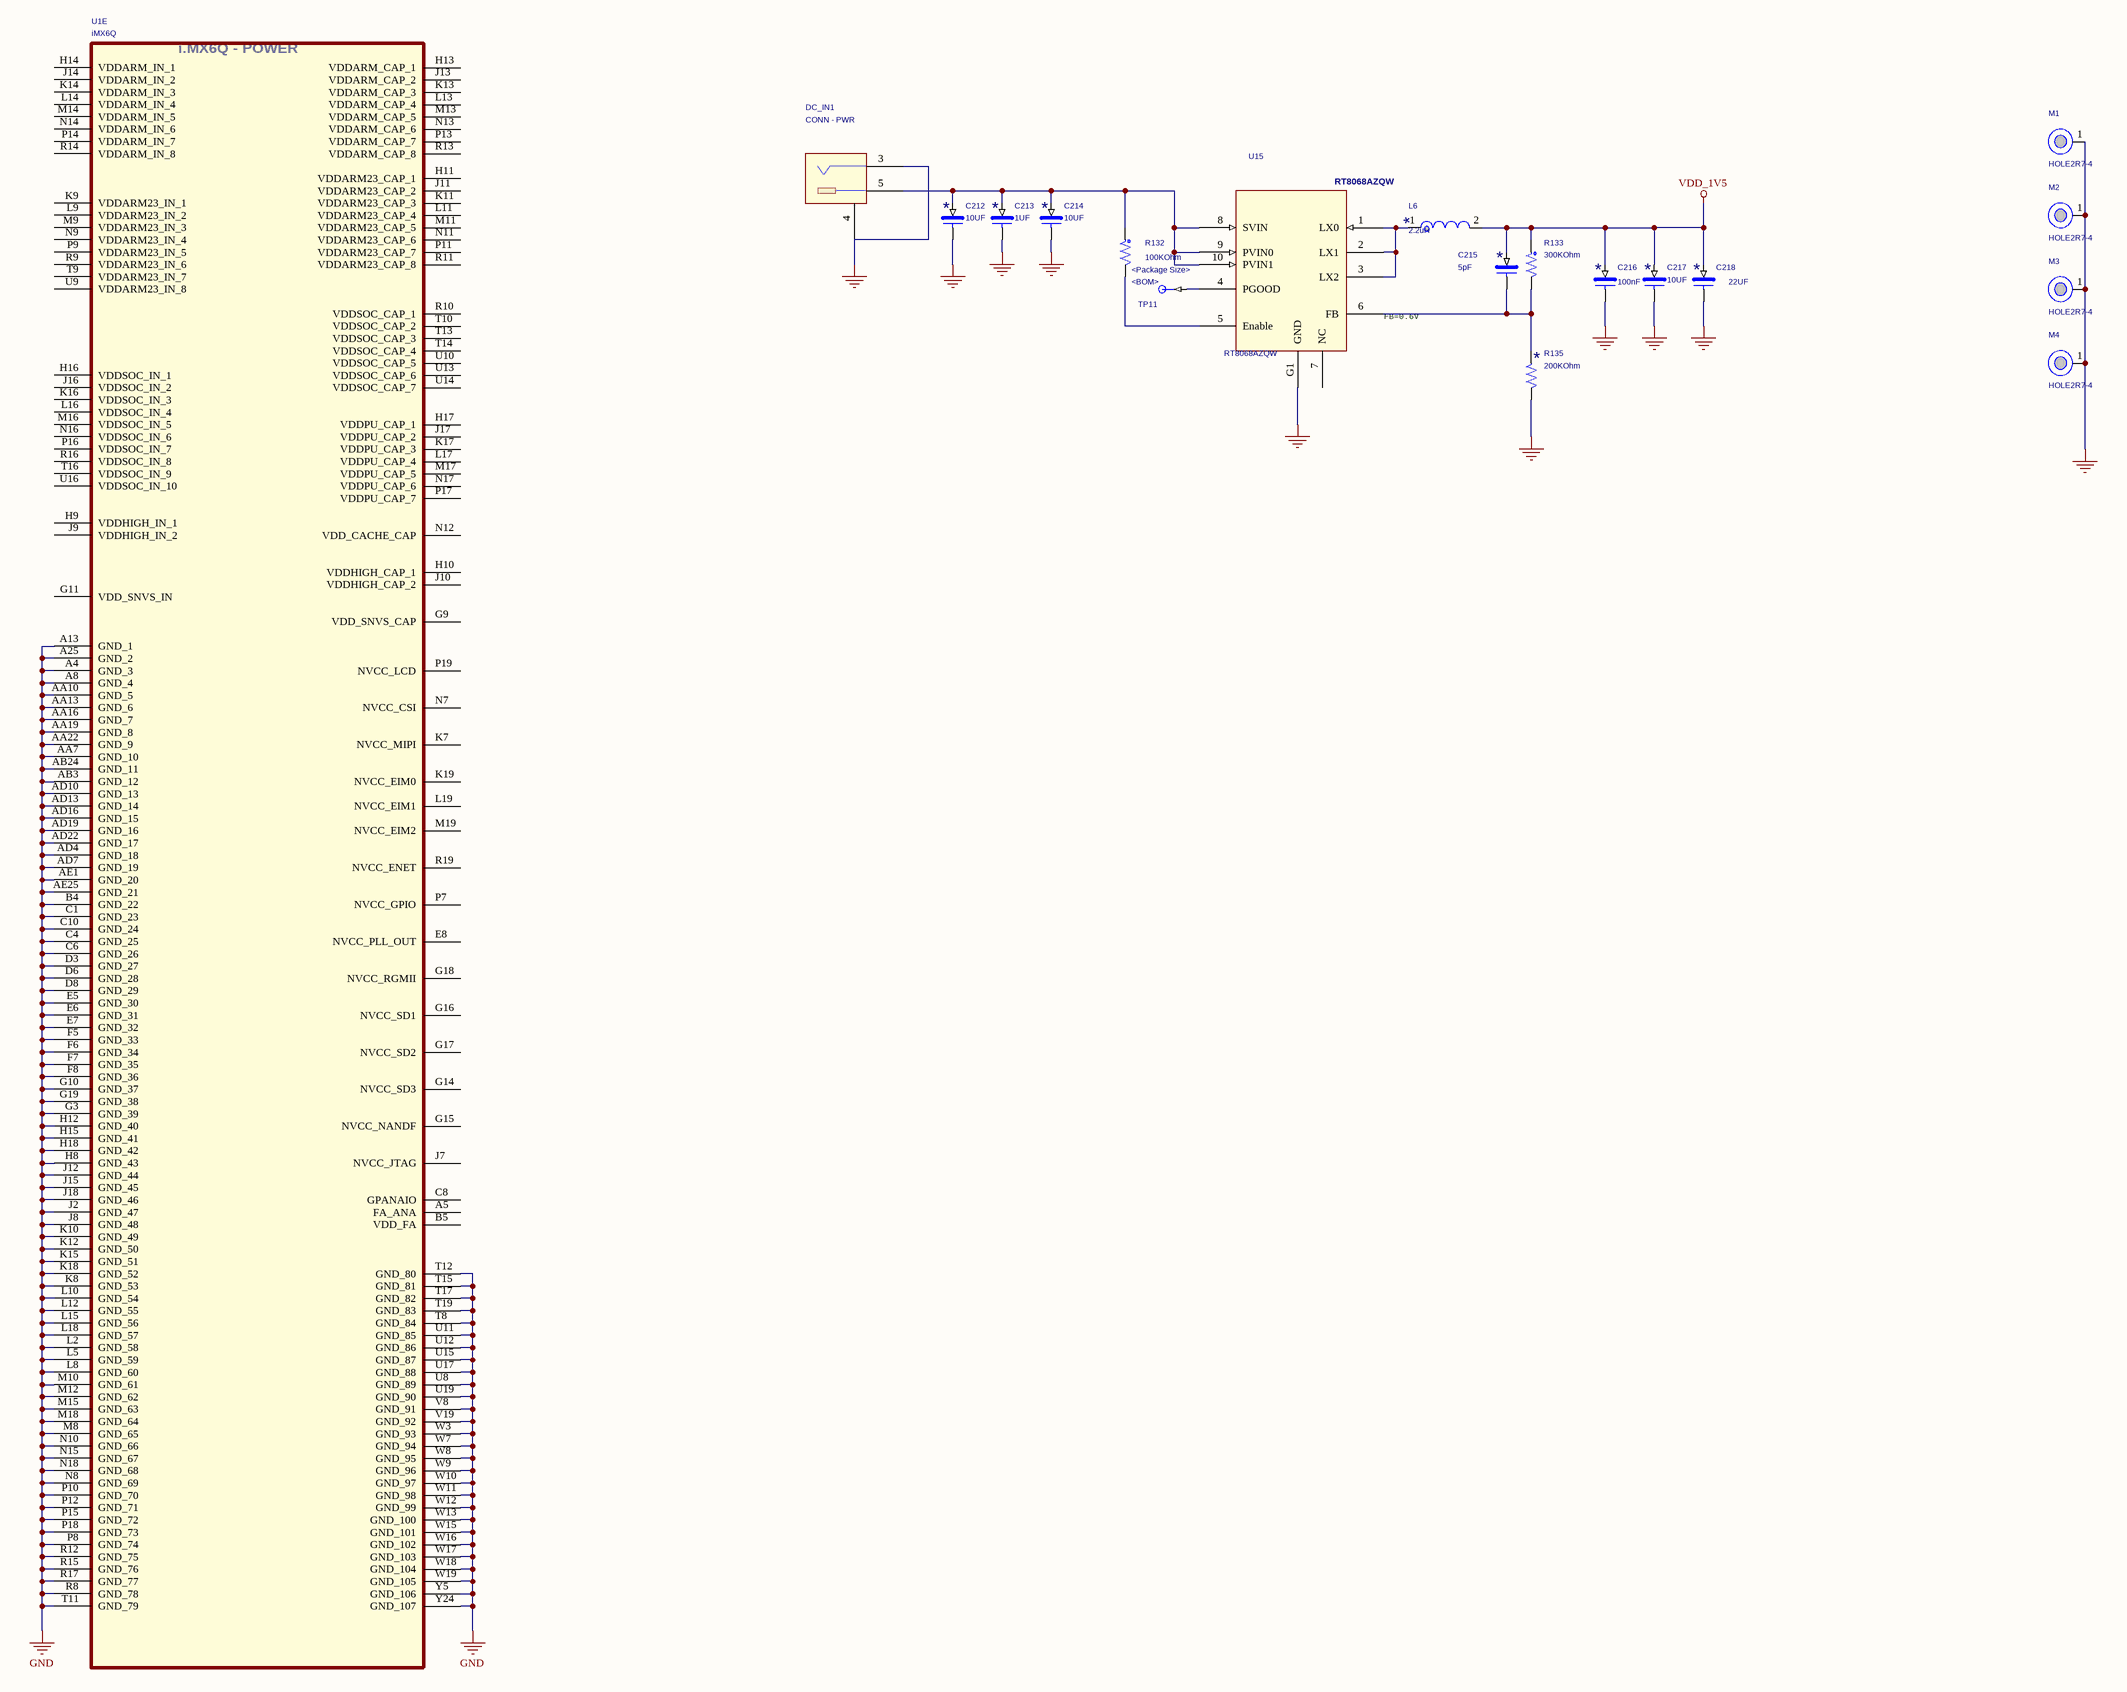
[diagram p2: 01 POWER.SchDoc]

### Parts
C212  10UF  [c0603]
C213  1UF  [c0402]
C214  10UF  [c0603]
C215  5pF  [C0402]
C216  100nF  [C0402]
C217  10UF  [c0603]
C218  22UF  [c0805]
DC_IN1  CONN - PWR  [dcj143x90h110]
L6  2.2uH  [l2_5r0x5r0_lqh]
M1  HOLE2R7-4  [pad_3_2mm]
M2  HOLE2R7-4  [pad_3_2mm]
M3  HOLE2R7-4  [pad_3_2mm]
M4  HOLE2R7-4  [pad_3_2mm]
R132  100KOhm  Package Size: <Package Size>  BOM: <BOM>  [R0402]
R133  300KOhm  [R0402]
R135  200KOhm  [R0402]
TP11  TP  [TP]  (value not drawn)
U1  iMX6Q  [skt_bga625_0p8_22x22]  (part E of 12)
U15  RT8068AZQW  [dfn11ch8]

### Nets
GND: C212.2 C213.2 C214.2 C216.2 C217.2 C218.2 DC_IN1.3 DC_IN1.4(GND1) M1.1 M2.1 M3.1 M4.1 R135.2 U1.A4(GND_3) U1.A8(GND_4) U1.A13(GND_1) U1.A25(GND_2) U1.AA7(GND_10) U1.AA10(GND_5) U1.AA13(GND_6) U1.AA16(GND_7) U1.AA19(GND_8) U1.AA22(GND_9) U1.AB3(GND_12) U1.AB24(GND_11) U1.AD4(GND_18) U1.AD7(GND_19) U1.AD10(GND_13) U1.AD13(GND_14) U1.AD16(GND_15) U1.AD19(GND_16) U1.AD22(GND_17) U1.AE1(GND_20) U1.AE25(GND_21) U1.B4(GND_22) U1.C1(GND_23) U1.C4(GND_25) U1.C6(GND_26) U1.C10(GND_24) U1.D3(GND_27) U1.D6(GND_28) U1.D8(GND_29) U1.E5(GND_30) U1.E6(GND_31) U1.E7(GND_32) U1.F5(GND_33) U1.F6(GND_34) U1.F7(GND_35) U1.F8(GND_36) U1.G3(GND_39) U1.G10(GND_37) U1.G19(GND_38) U1.H8(GND_43) U1.H12(GND_40) U1.H15(GND_41) U1.H18(GND_42) U1.J2(GND_47) U1.J8(GND_48) U1.J12(GND_44) U1.J15(GND_45) U1.J18(GND_46) U1.K8(GND_53) U1.K10(GND_49) U1.K12(GND_50) U1.K15(GND_51) U1.K18(GND_52) U1.L2(GND_58) U1.L5(GND_59) U1.L8(GND_60) U1.L10(GND_54) U1.L12(GND_55) U1.L15(GND_56) U1.L18(GND_57) U1.M8(GND_65) U1.M10(GND_61) U1.M12(GND_62) U1.M15(GND_63) U1.M18(GND_64) U1.N8(GND_69) U1.N10(GND_66) U1.N15(GND_67) U1.N18(GND_68) U1.P8(GND_74) U1.P10(GND_70) U1.P12(GND_71) U1.P15(GND_72) U1.P18(GND_73) U1.R8(GND_78) U1.R12(GND_75) U1.R15(GND_76) U1.R17(GND_77) U1.T8(GND_84) U1.T11(GND_79) U1.T12(GND_80) U1.T15(GND_81) U1.T17(GND_82) U1.T19(GND_83) U1.U8(GND_89) U1.U11(GND_85) U1.U12(GND_86) U1.U15(GND_87) U1.U17(GND_88) U1.U19(GND_90) U1.V8(GND_91) U1.V19(GND_92) U1.W3(GND_93) U1.W7(GND_94) U1.W8(GND_95) U1.W9(GND_96) U1.W10(GND_97) U1.W11(GND_98) U1.W12(GND_99) U1.W13(GND_100) U1.W15(GND_101) U1.W16(GND_102) U1.W17(GND_103) U1.W18(GND_104) U1.W19(GND_105) U1.Y5(GND_106) U1.Y24(GND_107) U15.G1(GND)
VDD_1V5: C215.1 C216.1 C217.1 C218.1 L6.2 R133.1
NetC212_1: C212.1 C213.1 C214.1 DC_IN1.5 R132.1 U15.8(SVIN) U15.9(PVIN0) U15.10(PVIN1)
NetC215_2: C215.2 R133.2 R135.1 U15.6(FB)
NetL6_1: L6.1 U15.1(LX0) U15.2(LX1) U15.3(LX2)
NetR132_2: R132.2 U15.5(Enable)
NetTP11_1: TP11.1 U15.4(PGOOD)

Not connected (* = marked no-connect by the designer): U1 A5(FA_ANA) B5(VDD_FA) C8(GPANAIO) E8(NVCC_PLL_OUT) G9(VDD_SNVS_CAP) G11(VDD_SNVS_IN) G14(NVCC_SD3) G15(NVCC_NANDF) G16(NVCC_SD1) G17(NVCC_SD2) G18(NVCC_RGMII) H9(VDDHIGH_IN_1) H10(VDDHIGH_CAP_1) H11(VDDARM23_CAP_1) H13(VDDARM_CAP_1) H14(VDDARM_IN_1) H16(VDDSOC_IN_1) H17(VDDPU_CAP_1) J7(NVCC_JTAG) J9(VDDHIGH_IN_2) J10(VDDHIGH_CAP_2) J11(VDDARM23_CAP_2) J13(VDDARM_CAP_2) J14(VDDARM_IN_2) J16(VDDSOC_IN_2) J17(VDDPU_CAP_2) K7(NVCC_MIPI) K9(VDDARM23_IN_1) K11(VDDARM23_CAP_3) K13(VDDARM_CAP_3) K14(VDDARM_IN_3) K16(VDDSOC_IN_3) K17(VDDPU_CAP_3) K19(NVCC_EIM0) L9(VDDARM23_IN_2) L11(VDDARM23_CAP_4) L13(VDDARM_CAP_4) L14(VDDARM_IN_4) L16(VDDSOC_IN_4) L17(VDDPU_CAP_4) L19(NVCC_EIM1) M9(VDDARM23_IN_3) M11(VDDARM23_CAP_5) M13(VDDARM_CAP_5) M14(VDDARM_IN_5) M16(VDDSOC_IN_5) M17(VDDPU_CAP_5) M19(NVCC_EIM2) N7(NVCC_CSI) N9(VDDARM23_IN_4) N11(VDDARM23_CAP_6) N12(VDD_CACHE_CAP) N13(VDDARM_CAP_6) N14(VDDARM_IN_6) N16(VDDSOC_IN_6) N17(VDDPU_CAP_6) P7(NVCC_GPIO) P9(VDDARM23_IN_5) P11(VDDARM23_CAP_7) P13(VDDARM_CAP_7) P14(VDDARM_IN_7) P16(VDDSOC_IN_7) P17(VDDPU_CAP_7) P19(NVCC_LCD) R9(VDDARM23_IN_6) R10(VDDSOC_CAP_1) R11(VDDARM23_CAP_8) R13(VDDARM_CAP_8) R14(VDDARM_IN_8) R16(VDDSOC_IN_8) R19(NVCC_ENET) T9(VDDARM23_IN_7) T10(VDDSOC_CAP_2) T13(VDDSOC_CAP_3) T14(VDDSOC_CAP_4) T16(VDDSOC_IN_9) U9(VDDARM23_IN_8) U10(VDDSOC_CAP_5) U13(VDDSOC_CAP_6) U14(VDDSOC_CAP_7) U16(VDDSOC_IN_10); U15 7(NC)

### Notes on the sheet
- (near U15) FB=0.6V

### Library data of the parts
C212 = CC0603MRX5R5BB106: CAP,10uF,+/-20%,X5R,10V,G,SMD0603; Mfg Part Number: LMK107BJ106MALTD; Part Number: 62010L000-011-G; Foxconn Part Number: 620112400-023-G; Tolerance: 6.3V,X5R,+/-20%; Mfg: TAIYO; CCL: for MID; Sub System: Reserved; Approval Status: E; Relex Category: 4; Relex Subcategory: 3; ONLY_DATASHEETNAME: YAGEO_CC0603MRX5R5BB106_DS.pdf; HHPN: STDPN; VPN: 620112400-VPN-G
C213 = CAP: CAP,1uF,+/-10%,X5R,10V,G,SMD0402; Mfg Part Number: GRM155R61A105K; Part Number: 62-01020084-00-015; Foxconn Part Number: 62010JJ00-015-G; Tolerance: 6.3V,X5R,+/-10%; Item Status: E; Mfg: MURATA; Sub System: Reserved; Relex Category: 4; Relex Subcategory: 1; ONLY_DATASHEETNAME: MURATA_GRM155R60J105KE19D_DS.pdf; PCB_FOOTPRINT_BEFORE: c0402h5; KEYID: 20050721-82649; VPN: 62010JJ00-VPN-G
C214 = GRM188R60J475K: CAP,4.7uF,+/-10%,X5R,6.3V,G,SMD0603; Foxconn Part Number: 62010BP00-015-G; Item Status: A; VPN: 62010BP00-VPN-G; PBDE: 5; Green State: C5; HHPN: 62-01020086-00-015; PCB_FOOTPRINT_BEFORE: c0603h8; ONLY_DATASHEETNAME: MURATA_GRM188R60J475K_DS.pdf; Remark: Reserved; Relex Subcategory: 1; Relex Category: 4; CCL: LF; Mfg: MURATA
C215 = CAP: CAP,5pF,+/-0.25pF,NPO(C0G),25V,G,SMD0201; Mfg Part Number: GRM0335C1E5R0CD01D; Part Number: GRM1555C1H5R0C; Foxconn Part Number: 62011SB00-015-G; Item Status: E; Mfg: MURATA; Sub System: Reserved; Relex Category: 4; ONLY_DATASHEETNAME: MURATA_GRM1555C1H5R0C_DS.pdf; HHPN: STDPN; KEYID: 20070118-16031; VPN: 62011SB00-VPN-G
C216 = CAP: CAP,100nF,+/-10%,X5R,10V,G,SMD0201; Foxconn Part Number: 620112U00-011-G; Part Number: 62-01030380-00-011; Mfg Part Number: CC0201KRX5R6BB104; Tolerance: 16V, X7R, +/-10%; Item Status: A; VPN: 620112U00-VPN-G; PBDE: 1000; CD: 100; Green State: C5; KEYID: 1667; HHPN: 62-01030380-00-011-G; ONLY_DATASHEETNAME: MLCC.pdf; Remark: Reserved; Relex Subcategory: 3; Relex Category: 4; Mfg: YAGEO
C217 = CC0603MRX5R5BB106: as C118 on sheet 02 DDR3 MEMORY
C218 = CC0603MRX5R5BB106: CAP,10uF,+/-20%,X5R,10V,G,SMD0603; Foxconn Part Number: 620112400-023-G; Part Number: 62010L000-011-G; Mfg Part Number: LMK107BJ106MALTD; Tolerance: 6.3V,X5R,+/-20%; Item Status: E; VPN: 620112400-VPN-G; HHPN: STDPN; ONLY_DATASHEETNAME: YAGEO_CC0603MRX5R5BB106_DS.pdf; Remark: Reserved; Relex Subcategory: 3; Relex Category: 4; CCL: for MID; Mfg: TAIYO
DC_IN1 = JPD1021-NB751-7F_0: CONN,I/O,Power Jack,R/A,Bla,G/F,G,DIP-3; Mfg Part Number: 2DC-G213I200; Part Number: 340415600-600-G; VPN: 340415U00-H59-G; Mfg: SINGATRON; Sub System: Reserved; Approval Status: E; Relex Category: 9; Relex Subcategory: 1; Remark: @DCIN; Only Datasheet Name: FOXCONN_JPD1021-NB751-7F_DS.pdf; HHPN: STDPN; Tolerance: <Tolerance>
L6 = PCMB042T-2R2MS_0: IND,2.2uH@100KHz,+/-30%,2.6A,36mOhm,SHLD,G,SMD; Foxconn Part Number: 63033K000-015-G; Part Number: 63031HQ00-034-G; Mfg Part Number: LQH5BPN2R2NT0L; Item Status: E; VPN: 63033K000-VPN-G; HHPN: STDPN; ONLY_DATASHEETNAME: CYNTEC_PCMB042T-2R2MS_DS.pdf; Remark: Reserved; Relex Subcategory: 2; Relex Category: 5; Tolerance: +/-20%; CCL: for MID; Mfg: MURATA
M1-M4 = MNTHOLE_3.2
R132 = RC0201JR-07100KL: RES,100KOhm,+/-1%,1/20W,G,SMD0201; Foxconn Part Number: 61011E300-011-G; Part Number: 61011ES00-011-G; Mfg Part Number: RC0201FR-07100KL; HHPN: STDPN; ONLY_DATASHEETNAME: YAGEO_RC0201JR-07100KL_DS.rar; Remark: Reserved; Relex Subcategory: 2; Relex Category: 3; Approval Status: E; Mfg: YAGEO
R133 = RC0402FR-07150KL: RES,300KOhm,+/-1%,1/20W,G,SMD0201; Foxconn Part Number: 61012W600-011-G; Mfg Part Number: RC0201FR-07300KL; VPN: 61012W600-VPN-G; PBDE: 1000; CD: 100; Green State: C5; KEYID: 20060609-111810; HHPN: 61-01002463-01-011; PCB_FOOTPRINT_BEFORE: r0402h4; ONLY_DATASHEETNAME: YAGEO_RC0402FR_07150KL_DS.pdf; Remark: Reserved; Relex Subcategory: 2; Relex Category: 3; Approval Status: E; CCL: RoHS; Mfg: YAGEO
R135 = RC0402FR-07100KL: RES,200KOhm,+/-1%,1/20W,G,SMD0201; Foxconn Part Number: 61011VW00-011-G; Mfg Part Number: RC0201FR-07200KL; VPN: 61011VW00-VPN-G; PBDE: 1000; CD: 100; Green State: C5; KEYID: 20051019-14316; HHPN: 61-01000550-03-011-G; PCB_FOOTPRINT_BEFORE: r0402h4; ONLY_DATASHEETNAME: YAGEO_RC0402FR_07100KL_DS.pdf; Remark: Reserved; Relex Subcategory: 2; Relex Category: 3; Approval Status: E; Mfg: YAGEO
TP11 = TP_0: as TP2 on sheet 02 DDR3 MEMORY
U1 = PCIMX6Q6VV1A_0: IC MCU MX6QUAD ARM CORTEX-A9 FCLBGA624; AGILE_PN: 344-01218; MFG_NAME01: FREESCALE SEMICONDUCTOR; MFG_PN01: PCIMX6Q0AVT01A; CAD_APPROVED: Yes
U15 = RT9199PSP_5: IC,Regulator,RT8068AZQW,3A,1MHZ,G,WDFN-10,SMD; Foxconn Part Number: 32012EL00-264-G; Item Status: E; VPN: 32012EL00-VPN-G; PBDE: 1000; CD: 100; Green State: C6; KEYID: 20060510-112323; HHPN: 32-09400062-00; ONLY_DATASHEETNAME: RICHTEK_RT9199PSP_DS.pdf; Remark: Reserved; Relex Subcategory: 3; Relex Category: 1; Mfg: RICHTEK

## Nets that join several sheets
GND: 02 DDR3 MEMORY (166 pins), 01 POWER (121 pins)
VDD_1V5: 02 DDR3 MEMORY (153 pins), 01 POWER (6 pins)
